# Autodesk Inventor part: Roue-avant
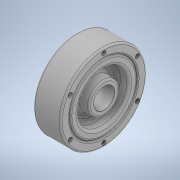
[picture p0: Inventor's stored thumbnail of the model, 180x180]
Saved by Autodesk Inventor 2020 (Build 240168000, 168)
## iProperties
Created: 1900-01
Part Number: Roue-avant
Material: Générique
Document SubType Name: Modeling
Designer: bruno
Density: 1 g/cm^3
Appearance: Par défaut
Mass: 188.822 g
Surface Area: 369.459 cm^2
Volume: 188.822 cm^3
Author: bruno
Revision Number: ANYUNSPECIFIED
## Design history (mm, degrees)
feature "Base1"
node "Plan de construction2"
sketch "Esquisse1"
  geometry: L1 (-18.078, -29.73)-(20.996, -29.73); L2 (20.996, -29.73)-(20.996, -36); L3 (14, -36)-(-14, -36); L4 (-18.078, -36)-(-18.078, -29.73); L5 (16.2, -74)-(-16.2, -74) reference; L6 (0, -74)-(0, -98); L7 (16.2, -98)-(-16.2, -98) reference; L8 (0, -86)-(16.2, -86); L9 (16.2, -74)-(16.2, -98) reference; L10 (-16, -39.005)-(-16, -132.995) reference; L11 (16, -39.005)-(16, -132.995) reference; L12 (-16, -39.005)-(-16, -38); L13 (16, -39.005)-(16, -38); L14 (-16, -39.005)-(16, -39.005); A1 r 2 centre (-14, -38) between (-14, -36) and (-16, -38); A2 r 2 centre (14, -38) between (16, -38) and (14, -36); 1 further point
  constraints: 18 end point, 4 midpoint, 4 point on circle, 4 tangent, 3 parallel, 2 centre point, 2 horizontal, 2 perpendicular, 2 point on line, 1 equal radius
  dimensions: "d1" = 50 distance between parallel lines of L3 L8; "d2" = 2 radius of A1 (derived)
revolve "Révolution1" sketch "Esquisse1" stored, may be unused: angle "d3" = 90 deg
sketch "Esquisse2"
  geometry: L1 (0, 0)-(0, 50); C1 r 15.667 at (0, 0) reference; C2 r 2.5 at (0, 45); 2 further points
  constraints: 2 end point, 1 centre point, 1 point on line, 1 vertical, 1 vertical alignment, 1 other
  dimensions: "d7" = 5 diameter of C2; "d8" = 45 distance of L1.start C2.centre
extrude "Extrusion2" cut sketch "Esquisse2" distance "d9" = 100; taper "d10" = 0 deg
pattern_circular "Réseau circulaire1" dims angle "d12" = 360 deg
node "Solide1"
